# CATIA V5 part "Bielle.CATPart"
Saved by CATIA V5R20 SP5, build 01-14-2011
Part number: Bielle
Bounding box of the stored display mesh (mm): x -54.622 to 4.622, y -4.66 to 4.66, z 1 to 11
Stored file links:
  F:\nsarlin\Bielle.CATPart
  J:\IAO\Mecanisme_a_bielle_et_deux_coulisseaux.CATProduct
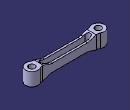
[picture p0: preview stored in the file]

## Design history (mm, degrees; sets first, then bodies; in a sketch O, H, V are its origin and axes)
External parameters (linked from other documents)
  External.Largeur = 7 mm
  External.Longueur_bielle = 50 mm
  External.Longueur_Axe = 8 mm
  External.Epaisseur = 20 mm
Set1
  Plane1 "Plan_de_ref": linked copy from another document
  Point1 "Point_coulisseau2": linked copy from another document
  Point2 "Point_coulisseau1": linked copy from another document
Body1 (main body)
  Sketch1 on Plane1, origin (0, 0, 0), H (1, 0, 0), V (0, 1, 0)
    line L1 (-45.3963, 3.5) -> (-4.6037, 3.5)
    arc A1 centre (-4.6037, 8.5) radius 5 from (-4.6037, 3.5) to (-2.2225, 4.1034) ccw
    arc A2 centre (0, 0) radius 4.6667 from (-2.2225, 4.1034) to (-2.2225, -4.1034) cw
    point P5 (0, 0)
    arc A3 centre (-4.6037, -8.5) radius 5 from (-2.2225, -4.1034) to (-4.6037, -3.5) ccw
    line L2 (-4.6037, -3.5) -> (-45.3963, -3.5)
    arc A4 centre (-45.3963, -8.5) radius 5 from (-45.3963, -3.5) to (-47.7775, -4.1034) ccw
    arc A5 centre (-50, 0) radius 4.6667 from (-47.7775, -4.1034) to (-47.7775, 4.1034) cw
    point P12 (-50, 0)
    arc A6 centre (-45.3963, 8.5) radius 5 from (-47.7775, 4.1034) to (-45.3963, 3.5) ccw
    reference projected point E1 (0, 0) from Point1
    reference projected point E2 (0, 0) from Point1
    reference projected point E3 (-50, 0) from Point2
    reference projected point E4 (-50, 0) from Point2
    point P15 (0, 27.3873)
    line L3 (-42, -2) -> (-8, -2)
    arc A7 centre (-8, 0) radius 2 from (-8, -2) to (-8, 2) ccw
    point P18 (-8, 0)
    line L4 (-8, 2) -> (-42, 2)
    arc A8 centre (-42, 0) radius 2 from (-42, 2) to (-42, -2) ccw
    reference projected point E5 (-50, 0) from Point2
    reference projected point E6 (0, 0) from Point1
    radius A6 = 5
    radius A4 = 5
    radius A5 = 4.6667 {= External.Largeur *2/3}
    radius A3 = 5
    radius A1 = 5
    radius A2 = 4.6667 {= External.Largeur *2/3}
    distance L1 L2 = 7 {= External.Largeur}
    distance E2 L2 = 3.5 {= External.Largeur /2}
    distance L1 E4 = 3.5 {= External.Largeur /2}
    radius A7 = 2 {= External.Largeur /3.5}
    distance P18 L2 = 3.5 {= External.Largeur /2}
    radius A8 = 2 {= External.Largeur /3.5}
    distance A8 E5 = 6
    distance E6 A7 = 6
    tangency: A1 L1, A2 A1, A3 A2, A4 L2, A5 A4, A6 A5, A6 L1, L2 A3, A7 L3, L4 A7, A8 L4, L3 A8
    coincidence: P5 E1, P12 E3
    parallelism: L3 L2
  Pad1: profile Sketch1, direction (0, 0, 1), length 11 {= External.Epaisseur /2+1mm}
  Sketch2 on Plane1, origin (0, 0, 0), H (1, 0, 0), V (0, 1, 0)
    line L1 (80, 80) -> (80, -80)
    line L2 (80, -80) -> (-80, -80)
    line L3 (-80, -80) -> (-80, 80)
    line L4 (-80, 80) -> (80, 80)
    vertical: L1 V, L3 V
    horizontal: L2 H, L4 H
    equidistance: L1 L3 O, L2 L4 O
  Pocket1: profile Sketch2, direction (0, 0, 1), length 1
  Sketch3 on face of Pad1 from Sketch1.L1, origin (0, 3.5, 0), H (-1, 0, 0), V (0, 0, 1)
    axis line L1 (60, 6) -> (-20, 6)
    reference projected line E1 (4.6037, 11) -> (45.3963, 11) from edge [face of Pad1 from Sketch1.L1 | end face of Pad1]
    construction line L2 through (0, 12) direction (1, 0)
    point P3 (4.6037, 11.2)
    line L3 (4.6037, 11.2) -> (45.3963, 11.2)
    point P4 (45.3963, 11.2)
    line L4 (45.3963, 11.2) -> (40.3963, 9.3801)
    point P5 (40.3963, 9.3801)
    arc A1 centre (38.2403, 15.3035) radius 6.3035 from (40.3963, 9.3801) to (38.2403, 9) cw
    point P7 (38.2403, 9)
    line L5 (38.2403, 9) -> (11.7597, 9)
    point P8 (11.7597, 9)
    arc A2 centre (11.7597, 15.3035) radius 6.3035 from (11.7597, 9) to (9.6037, 9.3801) cw
    point P10 (9.6037, 9.3801)
    line L6 (9.6037, 9.3801) -> (4.6037, 11.2)
    reference projected line E2 (4.6037, 11) -> (45.3963, 11) from edge [face of Pad1 from Sketch1.L1 | end face of Pad1]
    reference projected line E3 (4.6037, 11) -> (45.3963, 11) from edge [face of Pad1 from Sketch1.L1 | end face of Pad1]
    point P11 (4.6037, 0.8)
    point P12 (45.3963, 0.8)
    point P13 (40.3963, 2.6199)
    point P15 (38.2403, 3)
    point P16 (11.7597, 3)
    point P18 (9.6037, 2.6199)
    line L7 (4.6037, 0.8) -> (45.3963, 0.8)
    line L8 (45.3963, 0.8) -> (40.3963, 2.6199)
    arc A3 centre (38.2403, -3.3035) radius 6.3035 from (40.3963, 2.6199) to (38.2403, 3) ccw
    line L9 (38.2403, 3) -> (11.7597, 3)
    arc A4 centre (11.7597, -3.3035) radius 6.3035 from (11.7597, 3) to (9.6037, 2.6199) ccw
    line L10 (9.6037, 2.6199) -> (4.6037, 0.8)
    reference projected line E4 (4.6037, 0) -> (4.6037, 11) from edge [face of Pad1 from Sketch1.L1 | face of Pad1 from Sketch1.A1]
    reference projected line E5 (45.3963, 0) -> (45.3963, 11) from edge [face of Pad1 from Sketch1.A6 | face of Pad1 from Sketch1.L1]
    reference projected line E6 (4.6037, 11) -> (45.3963, 11) from edge [face of Pad1 from Sketch1.L1 | end face of Pad1]
    reference projected line E7 (4.6037, 0) -> (4.6037, 11) from edge [face of Pad1 from Sketch1.L1 | face of Pad1 from Sketch1.A1]
    reference projected line E8 (45.3963, 0) -> (45.3963, 11) from edge [face of Pad1 from Sketch1.A6 | face of Pad1 from Sketch1.L1]
    distance L1 E1 = 5
    distance L5 E2 = 2
    distance L3 E3 = 0.2
    angle L4 L3 = 160
    angle L6 L3 = 160
    distance P10 E7 = 5
    distance P5 E8 = 5
    tangency: A1 L4, A2 L5, A2 L6, A1 L5
    symmetry: P3 P11 L1, P4 P12 L1, P5 P13 L1, P7 P15 L1, P8 P16 L1, P10 P18 L1, L3 L7 L1, L4 L8 L1, A1 A3 L1, L5 L9 L1, A2 A4 L1, L6 L10 L1
    coincidence: P3 E4, P4 E5
    parallelism: E6 L3, L3 L5
  Pocket2: profile Sketch3, direction (0, -1, 0), length 7 {= External.Largeur}
  Sketch4 on end face of Pad1, origin (0, 0, 11), H (0, -1, 0), V (-1, 0, 0)
    circle A1 centre (0, 50) radius 2.3333
    point P1 (0, 50)
    circle A2 centre (0, 0) radius 2.3333
    point P2 (0, 0)
    reference projected point E1 (0, 50) from Point2
    reference projected point E2 (0, 0) from Point1
    radius A2 = 2.3333 {= External.Largeur /3}
    radius A1 = 2.3333 {= External.Largeur /3}
    coincidence: P1 E1, E2 P2
  Pocket3: profile Sketch4, direction (0, 0, -1), length 10 {= External.Epaisseur /2}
